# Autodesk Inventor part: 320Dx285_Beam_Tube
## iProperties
Shininess: 64.0
Length Units: 11269
Angle Units: 11279
Time Units: 11290
Mass Units: 11283
Length Display Precision: 3
Angle Display Precision: 2
Compacted: True
Part Number: 320Dx285_Beam_Tube
Document SubType Name: Modeling
Created: 2004-07
Designer: John Blackburn
Manufacturer: Standard
Standards Organization: Custom
Density: 0.0
Volumn: 0.0
Area: 0.0
PropertySet Name: Model Information
Control State: 0
Master: False
Checked Out: False
Author: John Blackburn
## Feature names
1. Extrusion1
